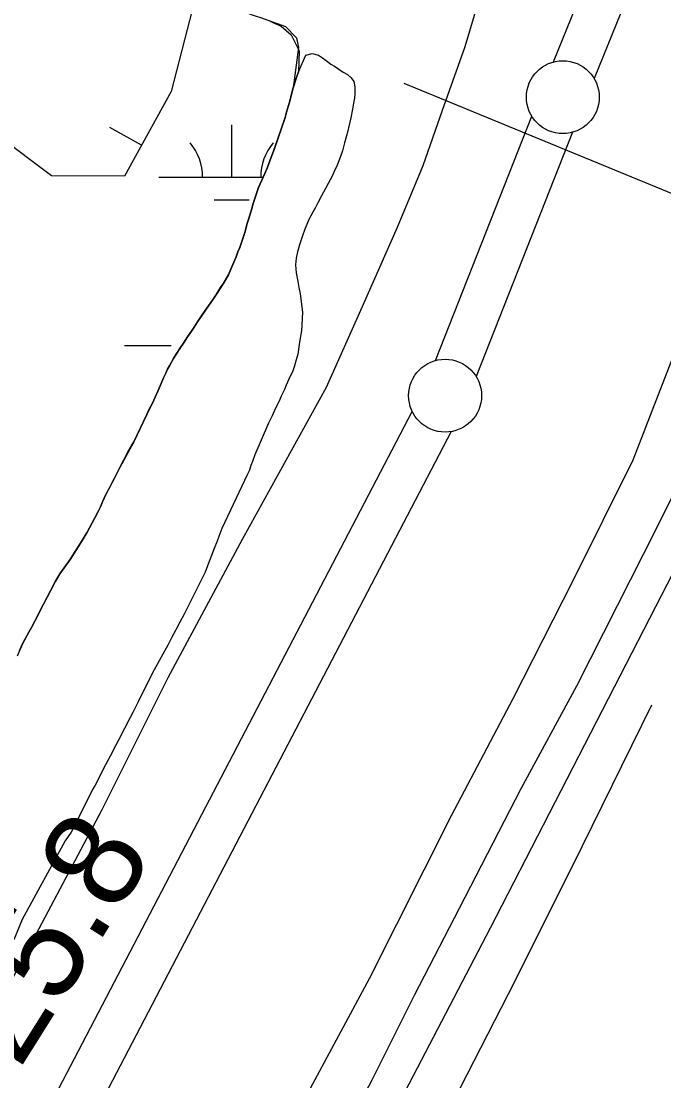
# Model space of a CAD drawing. Extents: x 3297735 to 3335592, y 670436 to 695807.
# Drawn here: x 3322161 to 3322601, y 691444 to 692171 of the extents above; entities that cross this region are included whole.
import ezdxf

# ---------------------------------------------------------------- set-up
doc = ezdxf.new("R2010")
doc.units = 0
for name, color, linetype in [('V-BORW-LINE', 7, 'Continuous'), ('V-LEVE-TOET', 7, 'Continuous'), ('V-RIVR-EDGE', 7, 'Continuous'), ('V-RIVR-RANG', 7, 'Continuous'), ('V-ROAD-CNTR', 7, 'Continuous'), ('V-SITE-VEGE', 7, 'Continuous'), ('V-SURV-LINE', 7, 'Continuous'), ('V-TOPO-SHOR', 7, 'Continuous'), ('V-UTIL-LINE', 7, 'Continuous'), ('V-WETL-SWMP', 7, 'Continuous')]:
    doc.layers.add(name, color=color, linetype=linetype)

msp = doc.modelspace()

# ---------------------------------------------------------------- linework, layer by layer
at = {"layer": 'V-BORW-LINE'}
msp.add_line((3322243.37, 692086.36), (3322221.49, 692098.45), dxfattribs=at)
msp.add_lwpolyline([(3322239.07, 692315.82), (3322288.7, 692305.28), (3322287.21, 692214.7), (3322263.67, 692123.09), (3322231.56, 692064.99), (3322181.62, 692065.23), (3322108.67, 692119.83), (3322114.59, 692186.56), (3322146.72, 692248.41), (3322239.07, 692315.82)], dxfattribs=at)
at = {"layer": 'V-LEVE-TOET'}
for points in [[(3322123.68, 691456.47), (3322166.91, 691537.4), (3322216.39, 691630.52), (3322261.45, 691721.12), (3322312.62, 691816.01), (3322370.1, 691920.34), (3322394.64, 691975.12), (3322418.74, 692030.14), (3322436.46, 692072.41), (3322449.69, 692110.27), (3322465.2, 692154.03), (3322484.48, 692218.61)], [(3322114.84, 690970.3), (3322175.17, 691085.37), (3322234.43, 691202.14), (3322291.83, 691310.26), (3322325.49, 691372.7), (3322360.71, 691442.41), (3322399.67, 691514.62), (3322455.94, 691626.5), (3322498.15, 691706.7), (3322539.3, 691787.58), (3322580.41, 691870.51), (3322602.18, 691926.48), (3322624.9, 691985.56), (3322646.82, 692049.79), (3322679, 692131.49), (3322708.44, 692212.77)]]:
    msp.add_lwpolyline(points, dxfattribs=at)
at = {"layer": 'V-RIVR-EDGE'}
msp.add_spline([(3319721.91, 688607.25), (3319733.2, 688627.78), (3319739.82, 688637.46), (3319746.04, 688644.42), (3319750.72, 688655.27), (3319752.28, 688659.14), (3319762.01, 688671.92), (3319781.47, 688699.79), (3319792.76, 688716.44), (3319801.32, 688726.89), (3319810.26, 688738.11), (3319819.98, 688747.01), (3319825.43, 688754.75), (3319830.49, 688762.88), (3319835.55, 688770.63), (3319840.23, 688780.31), (3319844.52, 688791.16), (3319846.86, 688795.42), (3319851.13, 688797.35), (3319854.24, 688799.66), (3319861.24, 688808.95), (3319869.41, 688820.96), (3319874.87, 688831.03), (3319884.99, 688845.35), (3319893.93, 688856.57), (3319900.54, 688860.82), (3319908.31, 688869.72), (3319918.43, 688881.33), (3319923.49, 688889.46), (3319928.16, 688897.21), (3319932.06, 688904.95), (3319939.44, 688912.69), (3319951.5, 688924.3), (3319955, 688930.88), (3319970.57, 688952.17), (3319976.4, 688958.36), (3319980.68, 688966.5), (3319987.3, 688976.95), (3319991.2, 688986.25), (3319997.81, 688992.82), (3320004.81, 689000.56), (3320006.38, 689006.76), (3320010.27, 689012.96), (3320018.06, 689024.96), (3320025.07, 689035.8), (3320031.68, 689044.71), (3320039.46, 689054.38), (3320044.52, 689060.57), (3320057.73, 689071.4), (3320064.34, 689077.2), (3320070.17, 689082.23), (3320074.45, 689090.36), (3320085.73, 689104.68), (3320093.52, 689116.3), (3320109.84, 689130.22), (3320125, 689144.14), (3320145.59, 689159.99), (3320166.96, 689177), (3320184.06, 689191.31), (3320194.55, 689197.87), (3320205.42, 689204.44), (3320211.64, 689209.85), (3320219.42, 689219.53), (3320234.59, 689238.11), (3320241.98, 689244.68), (3320253.64, 689257.45), (3320273.09, 689279.5), (3320283.99, 689297.32), (3320297.61, 689318.61), (3320312.03, 689344.56), (3320320.21, 689360.83), (3320328.41, 689380.97), (3320333.48, 689394.53), (3320349.85, 689425.9), (3320363.1, 689453.41), (3320368.17, 689465.42), (3320370.9, 689469.67), (3320379.06, 689477.41), (3320388.4, 689489.8), (3320394.62, 689499.09), (3320395.41, 689505.29), (3320397.76, 689513.82), (3320403.21, 689520.78), (3320409.04, 689527.75), (3320417.6, 689536.65), (3320423.43, 689544.39), (3320428.49, 689552.52), (3320431.24, 689564.54), (3320432.02, 689568.03), (3320442.14, 689581.19), (3320451.87, 689595.12), (3320462.77, 689612.93), (3320469.38, 689621.06), (3320477.55, 689631.51), (3320493.51, 689653.19), (3320500.9, 689665.19), (3320506.36, 689674.1), (3320514.54, 689688.82), (3320523.5, 689705.47), (3320534.4, 689723.28), (3320539.06, 689727.15), (3320544.9, 689735.28), (3320551.13, 689744.18), (3320556.58, 689752.7), (3320560.87, 689764.32), (3320568.26, 689774), (3320574.5, 689785.23), (3320578.79, 689794.53), (3320583.07, 689802.27), (3320590.86, 689815.83), (3320602.92, 689833.25), (3320613.43, 689849.12), (3320622.79, 689866.94), (3320636.42, 689890.17), (3320646.93, 689907.21), (3320658.22, 689926.96), (3320664.85, 689940.13), (3320664.87, 689948.66), (3320667.22, 689956.02), (3320676.55, 689968.02), (3320685.11, 689978.08), (3320691.73, 689991.25), (3320701.47, 690006.35), (3320706.14, 690016.04), (3320709.66, 690026.11), (3320715.89, 690035.79), (3320728.33, 690049.33), (3320741.18, 690068.69), (3320754.02, 690086.5), (3320761.81, 690100.44), (3320770.77, 690116.32), (3320777.39, 690127.16), (3320786.73, 690139.93), (3320794.89, 690149.22), (3320800.73, 690155.41), (3320806.18, 690166.26), (3320810.47, 690174), (3320820.98, 690192.59), (3320823.74, 690207.71), (3320829.97, 690218.16), (3320840.87, 690235.59), (3320854.1, 690256.5), (3320864.22, 690271.59), (3320869.28, 690277.01), (3320870.45, 690281.27), (3320876.68, 690289.4), (3320887.57, 690302.95), (3320901.57, 690319.98), (3320912.08, 690333.52), (3320919.47, 690342.43), (3320924.52, 690348.23), (3320932.3, 690356.35), (3320941.26, 690371.46), (3320956.44, 690393.91), (3320969.67, 690415.21), (3320973.57, 690422.57), (3320982.13, 690434.96), (3320987.2, 690444.64), (3320994.21, 690457.03), (3321000.83, 690467.87), (3321008.23, 690481.04), (3321017.97, 690500.02), (3321024.59, 690511.64), (3321030.43, 690518.6), (3321035.5, 690530.22), (3321040.94, 690537.19), (3321055.35, 690559.26), (3321068.58, 690577.84), (3321078.31, 690594.1), (3321086.87, 690605.72), (3321095.82, 690616.94), (3321102.82, 690625.84), (3321107.51, 690637.85), (3321113.34, 690645.6), (3321117.63, 690655.67), (3321123.87, 690670), (3321130.5, 690682.39), (3321142.57, 690701.37), (3321156.19, 690722.28), (3321168.65, 690743.19), (3321171.38, 690749.38), (3321176.05, 690754.41), (3321177.22, 690758.29), (3321181.12, 690767.2), (3321185.79, 690774.17), (3321192.03, 690789.28), (3321204.89, 690814.45), (3321214.25, 690834.98), (3321218.93, 690845.83), (3321223.61, 690855.12), (3321229.85, 690869.85), (3321238.03, 690883.79), (3321242.33, 690899.29), (3321247.41, 690912.46), (3321254.43, 690927.96), (3321263, 690946.55), (3321269.64, 690962.82), (3321273.93, 690973.67), (3321278.23, 690986.07), (3321286.44, 691015.52), (3321288.78, 691021.72), (3321293.84, 691028.3), (3321297.35, 691034.5), (3321303.19, 691045.34), (3321306.32, 691054.64), (3321308.29, 691066.66), (3321310.63, 691073.63), (3321314.52, 691079.44), (3321318.04, 691090.29), (3321320.01, 691103.08), (3321324.31, 691115.87), (3321326.26, 691120.13), (3321332.09, 691125.16), (3321336.76, 691133.68), (3321337.17, 691140.65), (3321337.18, 691146.47), (3321338.37, 691158.49), (3321341.12, 691172.44), (3321349.71, 691192.98), (3321372.69, 691236.35), (3321389.06, 691268.5), (3321398.41, 691284.38), (3321404.65, 691298.32), (3321407.38, 691307.24), (3321407.39, 691310.73), (3321407.79, 691316.15), (3321414.41, 691325.06), (3321416.76, 691334.75), (3321417.94, 691344.05), (3321422.24, 691356.06), (3321434.34, 691385.89), (3321448.39, 691422.7), (3321456.19, 691442.46), (3321462.05, 691458.34), (3321462.85, 691466.87), (3321467.91, 691477.72), (3321474.92, 691488.17), (3321481.15, 691497.85), (3321481.54, 691500.57), (3321489.74, 691519.94), (3321499.87, 691542.02), (3321510.79, 691564.87), (3321521.69, 691581.91), (3321529.1, 691598.18), (3321538.84, 691619.09), (3321550.12, 691632.64), (3321559.06, 691640.76), (3321566.84, 691650.44), (3321566.47, 691655.48), (3321567.25, 691659.74), (3321572.7, 691664.77), (3321581.26, 691676.38), (3321584.38, 691684.91), (3321587.11, 691693.43), (3321593.35, 691706.6), (3321601.92, 691721.7), (3321610.87, 691733.32), (3321617.87, 691739.5), (3321620.99, 691748.8), (3321624.5, 691755), (3321632.28, 691766.23), (3321637.34, 691773.97), (3321638.14, 691784.44), (3321641.66, 691795.29), (3321645.96, 691809.63), (3321651.03, 691820.47), (3321653.37, 691824.35), (3321658.42, 691828.99), (3321665.02, 691832.07), (3321673.18, 691838.64), (3321680.2, 691853.75), (3321683.72, 691866.15), (3321687.24, 691878.94), (3321691.93, 691892.5), (3321697.77, 691904.12), (3321704.38, 691909.54), (3321711, 691920.77), (3321724.23, 691939.74), (3321729.68, 691949.8), (3321733.59, 691959.49), (3321746.04, 691978.85), (3321765.1, 692000.13), (3321767.83, 692005.55), (3321769.01, 692012.53), (3321772.52, 692019.89), (3321782.64, 692034.6), (3321793.52, 692045.43), (3321802.86, 692057.43), (3321811.04, 692071.76), (3321820.77, 692085.31), (3321837.5, 692109.31), (3321852.67, 692125.56), (3321856.95, 692134.47), (3321865.51, 692146.08), (3321874.07, 692158.09), (3321882.62, 692162.33), (3321885.73, 692165.42), (3321887.31, 692179.77), (3321889.66, 692189.46), (3321896.67, 692199.14), (3321906.39, 692208.81), (3321914.56, 692218.87), (3321921.95, 692230.87), (3321931.31, 692249.47), (3321940.25, 692259.91), (3321951.52, 692266.48), (3321951.14, 692271.52), (3321953.48, 692276.17), (3321960.48, 692283.13), (3321960.49, 692288.17), (3321960.5, 692292.05), (3321966.73, 692300.96), (3321976.84, 692312.95), (3321985.4, 692326.12), (3321999.02, 692342.37), (3322004.07, 692347.79), (3322006.8, 692355.15), (3322018.86, 692369.86), (3322032.48, 692387.27), (3322035.98, 692394.25), (3322046.88, 692410.89), (3322053.89, 692419.41), (3322062.45, 692431.8), (3322080.36, 692459.29), (3322099.43, 692486.77), (3322109.15, 692500.71), (3322113.45, 692513.5), (3322120.08, 692527.44), (3322124.37, 692536.35), (3322130.59, 692544.09), (3322144.19, 692555.69), (3322154.3, 692563.42), (3322157.8, 692568.07), (3322157.81, 692573.5), (3322158.99, 692580.09), (3322165.23, 692595.2), (3322169.9, 692601), (3322176.9, 692609.9), (3322181.58, 692618.04), (3322185.48, 692627.33), (3322187.82, 692635.08), (3322190.16, 692638.96), (3322199.11, 692652.12), (3322206.11, 692660.24), (3322215.05, 692669.14), (3322221.67, 692679.21), (3322228.68, 692689.66), (3322230.65, 692701.29), (3322234.15, 692707.1), (3322239.98, 692713.68), (3322240.78, 692721.82), (3322246.62, 692732.28), (3322257.13, 692747.76), (3322269.19, 692761.31), (3322281.64, 692779.5), (3322287.08, 692784.53), (3322289.82, 692793.44), (3322298.4, 692811.26), (3322311.23, 692827.9), (3322325.25, 692849.2), (3322340.82, 692872.04), (3322357.55, 692894.49), (3322366.5, 692909.98), (3322374.67, 692919.27), (3322378.18, 692925.85), (3322378.19, 692932.44), (3322378.2, 692936.32), (3322380.16, 692941.75), (3322387.16, 692950.65), (3322397.3, 692972.73), (3322404.3, 692982.41), (3322407.81, 692990.54), (3322418.32, 693006.42), (3322430.38, 693021.51), (3322439.35, 693040.49), (3322447.92, 693056.37), (3322451.06, 693071.49), (3322451.87, 693088.16), (3322455.41, 693108.32), (3322461.66, 693123.43), (3322462.07, 693131.96), (3322461.33, 693147.08), (3322471.06, 693161.02), (3322480.02, 693177.67), (3322484.71, 693192.01), (3322487.85, 693207.9), (3322490.57, 693210.61), (3322500.3, 693224.93), (3322521.3, 693248.15), (3322539.95, 693264), (3322547.34, 693272.91), (3322550.08, 693282.59), (3322550.88, 693291.9), (3322552.45, 693297.71), (3322564.89, 693311.64), (3322570.72, 693318.61), (3322576.95, 693326.74), (3322580.47, 693340.69), (3322590.2, 693351.91), (3322600.3, 693359.25), (3322603.79, 693359.25), (3322609.2, 693353.42), (3322618.52, 693357.27), (3322625.13, 693363.85), (3322634.47, 693378.56), (3322653.93, 693404.88), (3322678.44, 693438.95), (3322692.84, 693458.69), (3322701, 693465.26), (3322708.76, 693467.96), (3322714.21, 693474.54), (3322719.66, 693481.51), (3322729.79, 693501.26), (3322740.68, 693515.19), (3322746.53, 693526.81), (3322752.77, 693541.92), (3322764.43, 693554.69), (3322769.49, 693562.82), (3322774.19, 693578.71), (3322781.2, 693591.1), (3322787.42, 693598.84), (3322795.21, 693610.46), (3322799.12, 693622.47), (3322801.47, 693634.49), (3322804.6, 693643.4), (3322808.49, 693648.82), (3322813.15, 693654.23), (3322817.07, 693670.51), (3322820.98, 693684.08), (3322828, 693699.57), (3322828.79, 693704.61), (3322829.58, 693711.2), (3322831.15, 693715.46), (3322838.93, 693727.85), (3322846.35, 693746.06), (3322854.15, 693763.88), (3322858.81, 693768.14), (3322865.03, 693775.88), (3322871.27, 693789.05), (3322877.11, 693797.95), (3322877.51, 693803.38), (3322881.8, 693810.74), (3322885.32, 693822.75), (3322886.52, 693837.48), (3322887.31, 693846.79), (3322888.49, 693852.22), (3322893.57, 693866.16), (3322903.7, 693885.14), (3322914.59, 693899.85), (3322916.94, 693906.83), (3322916.96, 693914.97), (3322915.81, 693921.56), (3322917, 693934.75), (3322920.53, 693950.25), (3322928.35, 693973.5), (3322938.09, 693991.7), (3322943.16, 694004.1), (3322945.88, 694005.64), (3322947.06, 694014.95), (3322947.71, 694018)], degree=3, dxfattribs=at)
at = {"layer": 'V-ROAD-CNTR'}
msp.add_lwpolyline([(3322644.23, 691863.8), (3322482.43, 691549.13), (3322187.26, 690983), (3322045.11, 690709.73)], dxfattribs=at)
at = {"layer": 'V-SITE-VEGE'}
for points in [[(3322217.39, 692213.36), (3322227.75, 692208.84), (3322239.21, 692204.53), (3322245.31, 692202.29), (3322248.82, 692201.27), (3322253.99, 692199.38), (3322272.27, 692193.39), (3322287.96, 692188.45), (3322292.21, 692186.9), (3322294.99, 692185.68), (3322299.61, 692183.96), (3322302.57, 692182.56), (3322307.38, 692180.66), (3322318.48, 692175.97), (3322321.99, 692174.77), (3322324.95, 692173.93), (3322342, 692167.82), (3322349.46, 692160.01)], [(3322349.46, 692160.01), (3322351.04, 692153.3), (3322347.25, 692125.69), (3322344.87, 692115.92), (3322342.78, 692109.02), (3322341.75, 692105.25), (3322332.3, 692077.99), (3322329.36, 692070.45), (3322323.56, 692057.36), (3322320.07, 692047.06), (3322318.46, 692041.29), (3322316.6, 692035.27), (3322315.44, 692031.87), (3322314.43, 692027.12), (3322310.7, 692016.06), (3322309.4, 692013.04), (3322308.23, 692009.78), (3322306.7, 692006), (3322304.57, 692001.34), (3322302.91, 691997.44), (3322299.2, 691991.25), (3322294.75, 691984.16), (3322281.62, 691965.17), (3322277.66, 691958.72), (3322274.88, 691954.8), (3322272, 691950.37), (3322269.95, 691947.45), (3322267.06, 691943.03), (3322265.26, 691939.99), (3322261.2, 691932.55), (3322258.47, 691926.75), (3322254.69, 691917.94), (3322252.55, 691913.53), (3322250.78, 691909.38), (3322246.85, 691901.56), (3322237.95, 691882.91), (3322228.52, 691865.25), (3322223.27, 691854.91), (3322218.86, 691846.7), (3322216.49, 691841.66), (3322215.07, 691838.27), (3322211.15, 691830.2), (3322206.01, 691820.86), (3322202.65, 691815.18), (3322194.36, 691802.15), (3322187.37, 691792.14), (3322184.13, 691786.71), (3322178.65, 691776.24), (3322176.02, 691771.44), (3322170.42, 691760.35), (3322161.71, 691744.19), (3322158.04, 691735.76)]]:
    msp.add_lwpolyline(points, dxfattribs=at)
at = {"layer": 'V-SURV-LINE'}
for points in [[(3322525.81, 692143.4), (3323020.05, 693360.86)], [(3323047.84, 693349.56), (3322553.6, 692132.1)], [(3322444.85, 691938.59), (3322510.9, 692106.15)], [(3322538.81, 692095.13), (3322472.75, 691927.58)], [(3321709.9, 690525.69), (3322428.93, 691903.71)], [(3322455.53, 691889.84), (3321736.49, 690511.82)]]:
    msp.add_lwpolyline(points, dxfattribs=at)
for centre in [(3322532.18, 692119.23), (3322451.47, 691914.49)]:
    msp.add_circle(centre, 25, dxfattribs=at)
at = {"layer": 'V-TOPO-SHOR'}
for points in [[(3322145.68, 690950.46), (3322178.86, 691014.35), (3322212.85, 691083.87), (3322265.47, 691184.76), (3322306.05, 691266), (3322340.54, 691327.42), (3322365.01, 691376.1), (3322401.51, 691445.06), (3322430.45, 691503.22), (3322461.23, 691562.98), (3322503.67, 691644.89), (3322541.69, 691715.45), (3322569.77, 691770.46), (3322596.33, 691823.26), (3322632.73, 691896.59), (3322663.05, 691962.28), (3322698.52, 692048.71), (3322727.23, 692129.67), (3322747.62, 692192.94)], [(3322356.02, 692148.03), (3322360.31, 692149.11), (3322364.67, 692148.15), (3322367.45, 692146.22), (3322369.86, 692144.41), (3322373.04, 692141.87), (3322375.69, 692140.44), (3322378.48, 692138.39), (3322381.64, 692136.34), (3322384.42, 692134.79), (3322387.08, 692132.6), (3322388.77, 692129.91), (3322389.47, 692126.31), (3322389.45, 692121.82), (3322389.28, 692118.58), (3322388.74, 692115.2), (3322387.96, 692111.07), (3322386.73, 692105.06), (3322385.95, 692101.06), (3322384.37, 692094.29), (3322382.53, 692087.9), (3322381.16, 692082.51), (3322379.63, 692078.61), (3322377.4, 692072.7), (3322375.38, 692068.29), (3322374.09, 692065.15), (3322371.34, 692060.1), (3322369.55, 692056.69), (3322366.81, 692051.64), (3322364.18, 692046.72), (3322362.51, 692043.57), (3322360.72, 692040.29), (3322358.1, 692035.24), (3322356.68, 692031.84), (3322355.26, 692028.7), (3322353.62, 692024.17), (3322351.65, 692018.02), (3322350.27, 692013.13), (3322349.37, 692008.87), (3322348.98, 692004.13), (3322349.35, 691998.78), (3322350.37, 691992.82), (3322351.09, 691988.6), (3322352.18, 691984.39), (3322353.6, 691971.84), (3322353.31, 691962.74), (3322352.91, 691958.99), (3322352.15, 691953.87), (3322351.38, 691949.49), (3322350.42, 691942.99), (3322349.39, 691938.97), (3322348.11, 691934.96), (3322346.71, 691930.81), (3322345.29, 691927.79), (3322342.44, 691921.62), (3322341.27, 691918.6), (3322339.01, 691914.06), (3322337.59, 691910.67), (3322335.21, 691906), (3322332.97, 691900.71), (3322330.47, 691895.67), (3322321.01, 691873.9), (3322319.37, 691869.37), (3322318.32, 691866.48), (3322317.27, 691863.46), (3322315.97, 691860.57), (3322298.4, 691823.28), (3322296.29, 691817.75), (3322295.11, 691814.73), (3322293.12, 691809.57), (3322290.89, 691803.66), (3322289.24, 691799.64), (3322287.02, 691793.36), (3322272.62, 691764.61), (3322269.63, 691759.19), (3322266.89, 691753.89), (3322263.9, 691748.46), (3322261.4, 691743.42), (3322250.76, 691724.23), (3322241.01, 691704.44), (3322239.23, 691700.78), (3322237.32, 691697.13), (3322235.53, 691693.72), (3322227.66, 691678.71), (3322225.63, 691674.8), (3322221.7, 691667.23), (3322218.6, 691661.18), (3322217.05, 691658.15), (3322213.48, 691651.09), (3322211.58, 691647.31), (3322209.54, 691643.77), (3322200.49, 691625.74), (3322195.01, 691615.15), (3322190.91, 691609.2), (3322161.41, 691555.18), (3322155.75, 691541.09)], [(3322267.06, 691943.03), (3322269.95, 691947.45), (3322272, 691950.37), (3322274.88, 691954.8), (3322277.66, 691958.72), (3322279.33, 691961.51), (3322281.62, 691965.17), (3322285.35, 691970.61), (3322289.21, 691976.19), (3322292.46, 691980.75), (3322294.75, 691984.17), (3322297.51, 691988.59), (3322299.2, 691991.25), (3322302.91, 691997.44), (3322304.57, 692001.34), (3322306.7, 692006), (3322308.23, 692009.78), (3322309.4, 692013.04), (3322310.7, 692016.06), (3322314.43, 692027.12), (3322315.44, 692031.87), (3322316.6, 692035.27), (3322318.46, 692041.29), (3322320.07, 692047.06), (3322323.56, 692057.36), (3322325.69, 692062.27), (3322327.82, 692066.93), (3322329.36, 692070.45), (3322332.3, 692077.99), (3322334.17, 692083.27), (3322341.75, 692105.25), (3322342.78, 692109.02), (3322344.87, 692115.92), (3322347.25, 692125.69), (3322349.69, 692133.35), (3322350.98, 692136.62), (3322356.02, 692148.03)], [(3322159.7, 691739.66), (3322161.71, 691744.19), (3322163.38, 691747.22), (3322166, 691752.27), (3322167.8, 691755.43), (3322170.42, 691760.35), (3322176.02, 691771.44), (3322178.65, 691776.24), (3322180.91, 691780.65), (3322184.13, 691786.71), (3322187.37, 691792.14), (3322194.36, 691802.15), (3322196.29, 691805.06), (3322199.41, 691809.99), (3322202.65, 691815.18), (3322206.01, 691820.86), (3322211.15, 691830.2), (3322213.52, 691835.12), (3322215.07, 691838.27), (3322216.49, 691841.66), (3322218.86, 691846.7), (3322220.65, 691849.98), (3322223.27, 691854.91), (3322224.83, 691857.93), (3322227.09, 691862.47), (3322228.52, 691865.25), (3322234.24, 691876.09), (3322237.95, 691882.91), (3322246.85, 691901.56), (3322248.4, 691904.71), (3322250.78, 691909.38), (3322252.55, 691913.53), (3322254.69, 691917.94), (3322256.82, 691922.85), (3322258.47, 691926.75), (3322259.78, 691929.52), (3322261.2, 691932.55), (3322262.75, 691935.32), (3322265.26, 691939.99), (3322267.06, 691943.03)], [(3322238.77, 691019.26), (3322271.3, 691076.46), (3322329.9, 691189.06), (3322386.66, 691299.74), (3322442.98, 691402.91), (3322494.97, 691504.1), (3322538.54, 691591.35), (3322593.3, 691702.4)]]:
    msp.add_lwpolyline(points, dxfattribs=at)
at = {"layer": 'V-UTIL-LINE'}
msp.add_lwpolyline([(3322736.37, 691961.24), (3322676.2, 692024.65), (3322423.36, 692128.57)], dxfattribs=at)
at = {"layer": 'V-WETL-SWMP'}
for p, q in [((3322331.32, 692171.35), (3322339.15, 692167.84)), ((3322339.15, 692167.84), (3322345.97, 692161.92)), ((3322345.97, 692161.92), (3322351.47, 692151.07)), ((3322351.47, 692151.07), (3322350.98, 692136.62)), ((3322350.98, 692136.62), (3322349.69, 692133.35)), ((3322349.69, 692133.35), (3322347.25, 692125.69)), ((3322347.25, 692125.69), (3322344.86, 692115.92)), ((3322344.86, 692115.92), (3322342.78, 692109.02)), ((3322341.75, 692105.26), (3322334.17, 692083.27)), ((3322342.78, 692109.02), (3322341.75, 692105.26)), ((3322305.12, 692064.33), (3322305.12, 692100.33)), ((3322334.17, 692083.27), (3322332.3, 692078)), ((3322332.3, 692078), (3322329.36, 692070.45)), ((3322329.36, 692070.45), (3322327.82, 692066.93)), ((3322255.12, 692064.33), (3322326.63, 692064.33)), ((3322325.69, 692062.27), (3322323.56, 692057.36)), ((3322327.82, 692066.93), (3322325.69, 692062.27)), ((3322323.56, 692057.36), (3322320.06, 692047.06)), ((3322293.12, 692048.9), (3322317.12, 692048.9)), ((3322320.06, 692047.06), (3322318.45, 692041.29)), ((3322318.45, 692041.29), (3322316.6, 692035.27)), ((3322316.6, 692035.27), (3322315.43, 692031.88)), ((3322314.42, 692027.12), (3322310.7, 692016.07)), ((3322315.43, 692031.88), (3322314.42, 692027.12)), ((3322309.4, 692013.04), (3322308.23, 692009.78)), ((3322310.7, 692016.07), (3322309.4, 692013.04)), ((3322306.7, 692006), (3322304.56, 692001.34)), ((3322308.23, 692009.78), (3322306.7, 692006)), ((3322302.91, 691997.44), (3322299.19, 691991.25)), ((3322304.56, 692001.34), (3322302.91, 691997.44)), ((3322297.51, 691988.59), (3322294.75, 691984.17)), ((3322299.19, 691991.25), (3322297.51, 691988.59)), ((3322294.75, 691984.17), (3322292.46, 691980.75)), ((3322289.21, 691976.19), (3322285.35, 691970.62)), ((3322292.46, 691980.75), (3322289.21, 691976.19)), ((3322285.35, 691970.62), (3322281.61, 691965.17)), ((3322279.33, 691961.51), (3322277.65, 691958.72)), ((3322281.61, 691965.17), (3322279.33, 691961.51)), ((3322274.88, 691954.8), (3322271.99, 691950.37)), ((3322277.65, 691958.72), (3322274.88, 691954.8)), ((3322231.71, 691948.9), (3322263.71, 691948.9)), ((3322269.94, 691947.45), (3322267.06, 691943.03)), ((3322271.99, 691950.37), (3322269.94, 691947.45)), ((3322265.26, 691939.99), (3322262.75, 691935.33)), ((3322267.06, 691943.03), (3322265.26, 691939.99)), ((3322261.2, 691932.55), (3322259.77, 691929.52)), ((3322262.75, 691935.33), (3322261.2, 691932.55)), ((3322258.47, 691926.75), (3322256.82, 691922.85)), ((3322259.77, 691929.52), (3322258.47, 691926.75)), ((3322254.69, 691917.94), (3322252.55, 691913.53)), ((3322256.82, 691922.85), (3322254.69, 691917.94)), ((3322250.78, 691909.38), (3322248.39, 691904.71)), ((3322252.55, 691913.53), (3322250.78, 691909.38)), ((3322246.85, 691901.56), (3322237.94, 691882.91)), ((3322248.39, 691904.71), (3322246.85, 691901.56)), ((3322237.94, 691882.91), (3322234.24, 691876.1)), ((3322234.24, 691876.1), (3322228.51, 691865.25)), ((3322228.51, 691865.25), (3322227.08, 691862.47)), ((3322224.82, 691857.93), (3322223.27, 691854.91)), ((3322227.08, 691862.47), (3322224.82, 691857.93)), ((3322223.27, 691854.91), (3322220.65, 691849.99)), ((3322218.86, 691846.71), (3322216.48, 691841.67)), ((3322220.65, 691849.99), (3322218.86, 691846.71)), ((3322215.07, 691838.27), (3322213.52, 691835.12)), ((3322216.48, 691841.67), (3322215.07, 691838.27)), ((3322211.14, 691830.2), (3322206.01, 691820.86)), ((3322213.52, 691835.12), (3322211.14, 691830.2)), ((3322202.65, 691815.18), (3322199.41, 691809.99)), ((3322206.01, 691820.86), (3322202.65, 691815.18)), ((3322199.41, 691809.99), (3322196.28, 691805.06)), ((3322194.36, 691802.15), (3322187.37, 691792.14)), ((3322196.28, 691805.06), (3322194.36, 691802.15)), ((3322184.13, 691786.71), (3322180.91, 691780.65)), ((3322187.37, 691792.14), (3322184.13, 691786.71)), ((3322180.91, 691780.65), (3322178.64, 691776.24)), ((3322176.02, 691771.44), (3322170.42, 691760.35)), ((3322178.64, 691776.24), (3322176.02, 691771.44)), ((3322170.42, 691760.35), (3322167.79, 691755.43)), ((3322166, 691752.27), (3322163.38, 691747.22)), ((3322167.79, 691755.43), (3322166, 691752.27)), ((3322161.7, 691744.2), (3322159.69, 691739.66)), ((3322163.38, 691747.22), (3322161.7, 691744.2))]:
    msp.add_line(p, q, dxfattribs=at)
for centre, start, end in [((3322249.88, 692064.81), 359.22818, 40.77184), ((3322360.36, 692064.81), 139.22818, 180.77184)]:
    msp.add_arc(centre, 35.25, start, end, dxfattribs=at)

# ---------------------------------------------------------------- texts
at = {"layer": 'V-RIVR-RANG'}
msp.add_text('25.8', height=67, rotation=57.93833, dxfattribs=at).set_placement((3322159.52, 691451.84))

doc.saveas('drawing.dxf')
